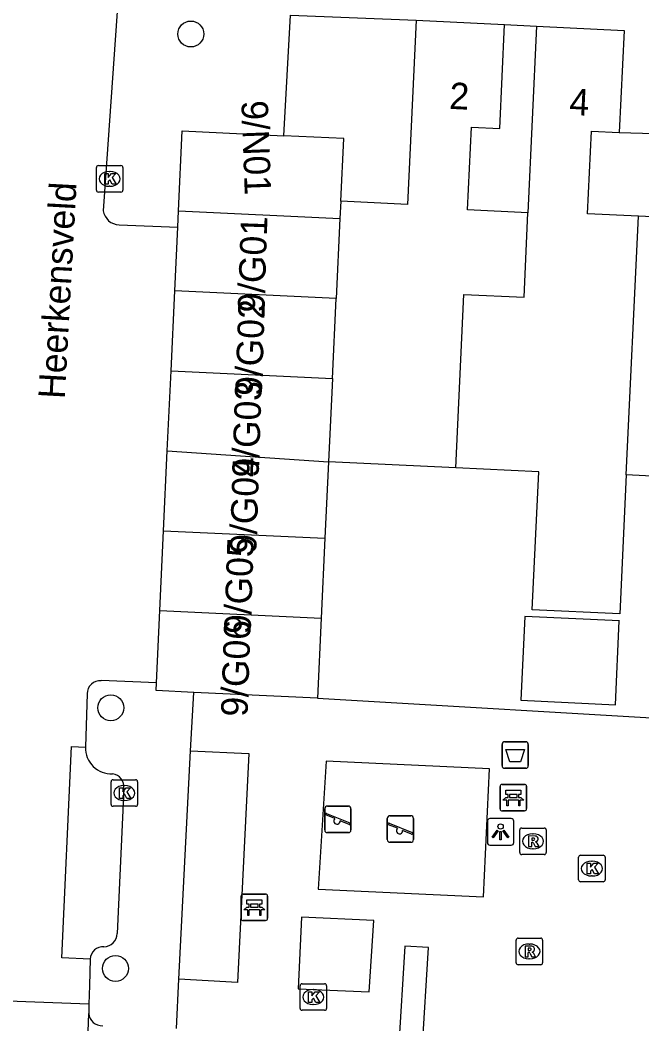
# Model space of a CAD drawing. Extents: x 162990 to 165007, y 383433 to 384336.
# Drawn here: x 164451.53 to 164474.99, y 383661.98 to 383699.84 of the extents above; entities that cross this region are included whole.
import ezdxf

# ---------------------------------------------------------------- set-up
doc = ezdxf.new("R2010")
doc.units = 0
for name, color, linetype in [('IMGEO_Afvalbak', 7, 'Continuous'), ('IMGEO_Bank', 7, 'Continuous'), ('IMGEO_Boom', 7, 'Continuous'), ('IMGEO_Kolk', 7, 'Continuous'), ('IMGEO_Lichtpunt', 7, 'Continuous'), ('IMGEO_Openbare_ruimte_label', 7, 'Continuous'), ('IMGEO_Pand', 7, 'Continuous'), ('IMGEO_Pand_nummerreeks', 7, 'Continuous'), ('IMGEO_Rijbaan_lokaal_open', 7, 'Continuous'), ('IMGEO_Rioolput', 7, 'Continuous'), ('IMGEO_Speelvoorziening', 7, 'Continuous'), ('IMGEO_Voetpad_open', 7, 'Continuous')]:
    doc.layers.add(name, color=color, linetype=linetype)

msp = doc.modelspace()

# ---------------------------------------------------------------- linework, layer by layer
at = {"layer": 'IMGEO_Afvalbak'}
for p, q in [((164469.816, 383672.619), (164470.606, 383672.619)), ((164470.606, 383672.619), (164469.816, 383672.619)), ((164469.716, 383671.719), (164469.716, 383672.519)), ((164469.716, 383672.519), (164469.716, 383671.719)), ((164470.706, 383672.519), (164470.706, 383671.719)), ((164470.706, 383671.719), (164470.706, 383672.519)), ((164470.606, 383671.619), (164469.816, 383671.619)), ((164469.816, 383671.619), (164470.606, 383671.619))]:
    msp.add_line(p, q, dxfattribs=at)
msp.add_lwpolyline([(164469.859, 383672.333), (164470.563, 383672.333), (164470.414, 383671.863), (164470.008, 383671.863), (164469.859, 383672.333)], dxfattribs=at)
for centre, start, end in [((164469.816, 383672.519), 90, 180), ((164469.816, 383672.519), 90, 180), ((164470.606, 383672.519), 0, 90), ((164470.606, 383672.519), 360, 90), ((164469.816, 383671.719), 180, 270), ((164469.816, 383671.719), 180, 270), ((164470.606, 383671.719), 270, 0), ((164470.606, 383671.719), 270, 0)]:
    msp.add_arc(centre, 0.1, start, end, dxfattribs=at)
at = {"layer": 'IMGEO_Bank'}
for p, q in [((164469.642, 383670.089), (164469.642, 383670.93)), ((164469.642, 383670.93), (164469.642, 383670.089)), ((164469.717, 383671.014), (164470.558, 383671.014)), ((164470.558, 383671.014), (164469.717, 383671.014)), ((164470.642, 383670.939), (164470.642, 383670.098)), ((164470.642, 383670.098), (164470.642, 383670.939)), ((164470.339, 383670.412), (164469.946, 383670.412)), ((164469.951, 383670.52), (164469.951, 383670.626)), ((164469.995, 383670.626), (164469.995, 383670.52)), ((164470.283, 383670.632), (164470.001, 383670.632)), ((164470.001, 383670.514), (164470.283, 383670.514)), ((164470.289, 383670.52), (164470.289, 383670.626)), ((164470.333, 383670.626), (164470.333, 383670.52)), ((164470.567, 383670.014), (164469.726, 383670.014)), ((164469.726, 383670.014), (164470.567, 383670.014)), ((164459.87, 383665.953), (164459.87, 383666.794)), ((164459.87, 383666.794), (164459.87, 383665.953)), ((164459.945, 383666.878), (164460.786, 383666.878)), ((164460.786, 383666.878), (164459.945, 383666.878)), ((164460.87, 383666.803), (164460.87, 383665.962)), ((164460.87, 383665.962), (164460.87, 383666.803)), ((164460.567, 383666.276), (164460.174, 383666.276)), ((164460.179, 383666.384), (164460.179, 383666.49)), ((164460.223, 383666.49), (164460.223, 383666.384)), ((164460.511, 383666.496), (164460.229, 383666.496)), ((164460.229, 383666.378), (164460.511, 383666.378)), ((164460.517, 383666.384), (164460.517, 383666.49)), ((164460.561, 383666.49), (164460.561, 383666.384)), ((164460.795, 383665.878), (164459.954, 383665.878)), ((164459.954, 383665.878), (164460.795, 383665.878))]:
    msp.add_line(p, q, dxfattribs=at)
for points in [[(164469.945, 383670.632), (164469.859, 383670.632), (164469.859, 383670.793), (164470.422, 383670.793), (164470.422, 383670.632), (164470.339, 383670.632)], [(164469.889, 383670.412), (164469.747, 383670.412), (164469.859, 383670.514), (164469.945, 383670.514)], [(164469.939, 383670.405), (164469.939, 383670.198), (164469.896, 383670.198), (164469.896, 383670.405)], [(164470.339, 383670.514), (164470.422, 383670.514), (164470.534, 383670.412), (164470.395, 383670.412)], [(164470.389, 383670.405), (164470.389, 383670.198), (164470.345, 383670.198), (164470.345, 383670.405)], [(164460.173, 383666.496), (164460.087, 383666.496), (164460.087, 383666.657), (164460.65, 383666.657), (164460.65, 383666.496), (164460.567, 383666.496)], [(164460.117, 383666.276), (164459.975, 383666.276), (164460.087, 383666.378), (164460.173, 383666.378)], [(164460.167, 383666.269), (164460.167, 383666.062), (164460.124, 383666.062), (164460.124, 383666.269)], [(164460.567, 383666.378), (164460.65, 383666.378), (164460.762, 383666.276), (164460.623, 383666.276)], [(164460.617, 383666.269), (164460.617, 383666.062), (164460.573, 383666.062), (164460.573, 383666.269)]]:
    msp.add_lwpolyline(points, dxfattribs=at)
for centre, radius, start, end in [((164469.72, 383670.936), 0.0779, 92.4484, 184.2845), ((164469.72, 383670.936), 0.0779, 92.4484, 184.2845), ((164470.564, 383670.936), 0.0779, 2.4484, 94.2845), ((164470.564, 383670.936), 0.0779, 2.4484, 94.2845), ((164469.889, 383670.405), 0.00671, 2.8957, 87.1043), ((164469.946, 383670.405), 0.00671, 92.8957, 177.1043), ((164469.944, 383670.625), 0.00671, 2.8957, 87.1043), ((164469.944, 383670.521), 0.00671, 272.8957, 357.1043), ((164470.001, 383670.625), 0.00671, 92.8957, 177.1043), ((164470.001, 383670.521), 0.00671, 182.8957, 267.1043), ((164470.283, 383670.625), 0.00671, 2.8957, 87.1043), ((164470.283, 383670.521), 0.00671, 272.8957, 357.1043), ((164470.34, 383670.625), 0.00671, 92.8957, 177.1043), ((164470.34, 383670.521), 0.00671, 182.8957, 267.1043), ((164470.338, 383670.405), 0.00671, 2.8957, 87.1043), ((164470.395, 383670.405), 0.00671, 92.8957, 177.1043), ((164469.72, 383670.092), 0.0779, 182.4484, 274.2845), ((164469.72, 383670.092), 0.0779, 182.4484, 274.2845), ((164470.564, 383670.092), 0.0779, 272.4484, 4.2845), ((164470.564, 383670.092), 0.0779, 272.4484, 4.2845), ((164459.948, 383666.8), 0.0779, 92.4484, 184.2845), ((164459.948, 383666.8), 0.0779, 92.4484, 184.2845), ((164460.792, 383666.8), 0.0779, 2.4484, 94.2845), ((164460.792, 383666.8), 0.0779, 2.4484, 94.2845), ((164460.117, 383666.269), 0.00671, 2.8957, 87.1043), ((164460.174, 383666.269), 0.00671, 92.8957, 177.1043), ((164460.172, 383666.489), 0.00671, 2.8957, 87.1043), ((164460.172, 383666.385), 0.00671, 272.8957, 357.1043), ((164460.229, 383666.489), 0.00671, 92.8957, 177.1043), ((164460.229, 383666.385), 0.00671, 182.8957, 267.1043), ((164460.511, 383666.489), 0.00671, 2.8957, 87.1043), ((164460.511, 383666.385), 0.00671, 272.8957, 357.1043), ((164460.568, 383666.489), 0.00671, 92.8957, 177.1043), ((164460.568, 383666.385), 0.00671, 182.8957, 267.1043), ((164460.566, 383666.269), 0.00671, 2.8957, 87.1043), ((164460.623, 383666.269), 0.00671, 92.8957, 177.1043), ((164459.948, 383665.956), 0.0779, 182.4484, 274.2845), ((164459.948, 383665.956), 0.0779, 182.4484, 274.2845), ((164460.792, 383665.956), 0.0779, 272.4484, 4.2845), ((164460.792, 383665.956), 0.0779, 272.4484, 4.2845)]:
    msp.add_arc(centre, radius, start, end, dxfattribs=at)
at = {"layer": 'IMGEO_Boom'}
for centre in [(164457.973, 383699.31), (164454.955, 383673.902), (164455.129, 383664.071)]:
    msp.add_circle(centre, 0.489, dxfattribs=at)
at = {"layer": 'IMGEO_Kolk'}
for p, q in [((164454.411, 383693.421), (164454.411, 383694.273)), ((164454.486, 383694.347), (164455.338, 383694.347)), ((164455.412, 383694.273), (164455.412, 383693.421)), ((164454.899, 383694.127), (164454.924, 383694.127)), ((164454.922, 383693.567), (164454.897, 383693.567)), ((164455.338, 383693.347), (164454.486, 383693.347)), ((164454.964, 383670.26), (164454.964, 383671.112)), ((164455.039, 383671.186), (164455.891, 383671.186)), ((164455.965, 383671.112), (164455.965, 383670.26)), ((164455.452, 383670.966), (164455.477, 383670.966)), ((164455.475, 383670.406), (164455.45, 383670.406)), ((164455.891, 383670.186), (164455.039, 383670.186)), ((164472.604, 383667.412), (164472.604, 383668.264)), ((164472.679, 383668.338), (164473.531, 383668.338)), ((164473.092, 383668.118), (164473.117, 383668.118)), ((164473.605, 383668.264), (164473.605, 383667.412)), ((164473.531, 383667.338), (164472.679, 383667.338)), ((164473.115, 383667.558), (164473.09, 383667.558)), ((164462.095, 383662.566), (164462.095, 383663.418)), ((164462.17, 383663.492), (164463.022, 383663.492)), ((164462.583, 383663.272), (164462.608, 383663.272)), ((164463.096, 383663.418), (164463.096, 383662.566)), ((164463.022, 383662.492), (164462.17, 383662.492)), ((164462.606, 383662.712), (164462.581, 383662.712))]:
    msp.add_line(p, q, dxfattribs=at)
for points in [[(164454.411, 383693.421), (164454.411, 383694.273)], [(164454.486, 383694.347), (164455.338, 383694.347)], [(164455.412, 383694.273), (164455.412, 383693.421)], [(164454.732, 383694.047), (164454.855, 383694.047), (164454.855, 383693.896), (164454.985, 383694.047), (164455.149, 383694.047), (164455.003, 383693.896), (164455.156, 383693.647), (164455.004, 383693.647), (164454.919, 383693.811), (164454.855, 383693.744), (164454.855, 383693.647), (164454.732, 383693.647), (164454.732, 383694.047)], [(164455.338, 383693.347), (164454.486, 383693.347)], [(164454.964, 383670.26), (164454.964, 383671.112)], [(164455.039, 383671.186), (164455.891, 383671.186)], [(164455.965, 383671.112), (164455.965, 383670.26)], [(164455.285, 383670.886), (164455.408, 383670.886), (164455.408, 383670.735), (164455.538, 383670.886), (164455.702, 383670.886), (164455.556, 383670.735), (164455.709, 383670.486), (164455.557, 383670.486), (164455.472, 383670.65), (164455.408, 383670.583), (164455.408, 383670.486), (164455.285, 383670.486), (164455.285, 383670.886)], [(164455.891, 383670.186), (164455.039, 383670.186)], [(164472.604, 383667.412), (164472.604, 383668.264)], [(164472.679, 383668.338), (164473.531, 383668.338)], [(164473.605, 383668.264), (164473.605, 383667.412)], [(164472.925, 383668.038), (164473.048, 383668.038), (164473.048, 383667.887), (164473.178, 383668.038), (164473.342, 383668.038), (164473.196, 383667.887), (164473.349, 383667.638), (164473.197, 383667.638), (164473.112, 383667.802), (164473.048, 383667.735), (164473.048, 383667.638), (164472.925, 383667.638), (164472.925, 383668.038)], [(164473.531, 383667.338), (164472.679, 383667.338)], [(164462.095, 383662.566), (164462.095, 383663.418)], [(164462.17, 383663.492), (164463.022, 383663.492)], [(164462.416, 383663.192), (164462.539, 383663.192), (164462.539, 383663.041), (164462.669, 383663.192), (164462.833, 383663.192), (164462.687, 383663.041), (164462.84, 383662.792), (164462.688, 383662.792), (164462.603, 383662.956), (164462.539, 383662.889), (164462.539, 383662.792), (164462.416, 383662.792), (164462.416, 383663.192)], [(164463.096, 383663.418), (164463.096, 383662.566)], [(164463.022, 383662.492), (164462.17, 383662.492)]]:
    msp.add_lwpolyline(points, dxfattribs=at)
for centre, start, end in [((164454.488, 383694.271), 91.552, 178.448), ((164454.488, 383694.271), 91.552, 178.448), ((164455.336, 383694.271), 1.552, 88.448), ((164455.336, 383694.271), 1.552, 88.448), ((164454.488, 383693.423), 181.552, 268.448), ((164454.488, 383693.423), 181.552, 268.448), ((164455.336, 383693.423), 271.552, 358.448), ((164455.336, 383693.423), 271.552, 358.448), ((164455.041, 383671.11), 91.552, 178.448), ((164455.041, 383671.11), 91.552, 178.448), ((164455.889, 383671.11), 1.552, 88.448), ((164455.889, 383671.11), 1.552, 88.448), ((164455.041, 383670.262), 181.552, 268.448), ((164455.041, 383670.262), 181.552, 268.448), ((164455.889, 383670.262), 271.552, 358.448), ((164455.889, 383670.262), 271.552, 358.448), ((164472.681, 383668.262), 91.552, 178.448), ((164472.681, 383668.262), 91.552, 178.448), ((164473.529, 383668.262), 1.552, 88.448), ((164473.529, 383668.262), 1.552, 88.448), ((164472.681, 383667.414), 181.552, 268.448), ((164472.681, 383667.414), 181.552, 268.448), ((164473.529, 383667.414), 271.552, 358.448), ((164473.529, 383667.414), 271.552, 358.448), ((164462.172, 383663.416), 91.552, 178.448), ((164462.172, 383663.416), 91.552, 178.448), ((164463.02, 383663.416), 1.552, 88.448), ((164463.02, 383663.416), 1.552, 88.448), ((164462.172, 383662.568), 181.552, 268.448), ((164462.172, 383662.568), 181.552, 268.448), ((164463.02, 383662.568), 271.552, 358.448), ((164463.02, 383662.568), 271.552, 358.448)]:
    msp.add_arc(centre, 0.0765, start, end, dxfattribs=at)
for centre, major_axis, ratio, start_param, end_param in [((164454.898, 383693.847), (-0.387, 0.002), 0.722429, 4.712389, 7.853982), ((164454.923, 383693.847), (-0.39, 0.002), 0.717154, 1.570796, 4.712389), ((164455.451, 383670.686), (-0.387, 0.002), 0.722429, 4.712389, 7.853982), ((164455.476, 383670.686), (-0.39, 0.002), 0.717154, 1.570796, 4.712389), ((164473.091, 383667.838), (-0.387, 0.002), 0.722429, 4.712389, 7.853982), ((164473.116, 383667.838), (-0.39, 0.002), 0.717154, 1.570796, 4.712389), ((164462.582, 383662.992), (-0.387, 0.002), 0.722429, 4.712389, 7.853982), ((164462.607, 383662.992), (-0.39, 0.002), 0.717154, 1.570796, 4.712389)]:
    msp.add_ellipse(centre, major_axis=major_axis, ratio=ratio, start_param=start_param, end_param=end_param, dxfattribs=at)
at = {"layer": 'IMGEO_Lichtpunt'}
for p, q in [((164469.16, 383669.625), (164469.16, 383668.818)), ((164469.16, 383669.625), (164469.16, 383668.818)), ((164470.062, 383669.72), (164469.254, 383669.72)), ((164470.062, 383669.72), (164469.254, 383669.72)), ((164470.156, 383668.818), (164470.156, 383669.625)), ((164470.156, 383668.818), (164470.156, 383669.625)), ((164469.254, 383668.724), (164470.062, 383668.724)), ((164469.254, 383668.724), (164470.062, 383668.724))]:
    msp.add_line(p, q, dxfattribs=at)
for points in [[(164469.534, 383669.289), (164469.573, 383669.261), (164469.385, 383668.999), (164469.347, 383669.026), (164469.534, 383669.289)], [(164469.636, 383669.241), (164469.683, 383669.241), (164469.683, 383668.919), (164469.636, 383668.919), (164469.636, 383669.241)], [(164469.746, 383669.261), (164469.784, 383669.288), (164469.971, 383669.026), (164469.932, 383668.998), (164469.746, 383669.261)]]:
    msp.add_lwpolyline(points, dxfattribs=at)
msp.add_circle((164469.659, 383669.423), 0.0994, dxfattribs=at)
for centre, start, end in [((164469.254, 383669.625), 90, 180), ((164469.254, 383669.625), 90, 180), ((164470.062, 383669.625), 0, 90), ((164470.062, 383669.625), 0, 90), ((164469.254, 383668.818), 180, 270), ((164469.254, 383668.818), 180, 270), ((164470.062, 383668.818), 270, 0), ((164470.062, 383668.818), 270, 360)]:
    msp.add_arc(centre, 0.0946, start, end, dxfattribs=at)
at = {"layer": 'IMGEO_Pand'}
for points in [[(164466.471, 383699.831), (164466.145, 383692.884), (164463.632, 383693.002)], [(164466.471, 383699.831), (164469.812, 383699.674)], [(164470.688, 383692.567), (164468.417, 383692.674), (164468.564, 383695.797), (164469.628, 383695.747), (164469.812, 383699.674)], [(164471.017, 383699.602), (164470.688, 383692.567)], [(164471.017, 383699.602), (164474.319, 383699.447), (164474.138, 383695.599)], [(164457.509, 383692.64), (164457.65, 383695.653), (164461.477, 383695.473)], [(164463.632, 383693.002), (164463.742, 383695.367), (164461.477, 383695.473)], [(164474.857, 383692.435), (164472.943, 383692.525), (164473.089, 383695.648), (164474.138, 383695.599)], [(164477.653, 383695.492), (164477.504, 383692.311), (164474.857, 383692.435)], [(164463.632, 383693.002), (164463.601, 383692.35)], [(164457.48, 383692.025), (164457.509, 383692.64)], [(164457.509, 383692.64), (164463.601, 383692.35)], [(164463.601, 383692.35), (164463.459, 383689.339)], [(164467.966, 383682.951), (164468.268, 383689.487), (164470.543, 383689.382), (164470.688, 383692.567)], [(164474.398, 383682.68), (164474.857, 383692.435)], [(164457.367, 383689.625), (164457.48, 383692.025)], [(164457.226, 383686.61), (164457.367, 383689.625)], [(164463.459, 383689.339), (164457.367, 383689.625)], [(164463.318, 383686.324), (164463.459, 383689.339)], [(164457.085, 383683.595), (164457.226, 383686.61)], [(164457.226, 383686.61), (164463.318, 383686.324)], [(164463.318, 383686.324), (164463.17, 383683.175)], [(164456.944, 383680.58), (164457.085, 383683.595)], [(164457.085, 383683.595), (164463.17, 383683.175)], [(164463.17, 383683.175), (164463.035, 383680.294)], [(164467.966, 383682.951), (164463.17, 383683.175)], [(164474.398, 383682.68), (164474.152, 383677.44), (164470.854, 383677.595), (164471.098, 383682.804), (164467.966, 383682.951)], [(164481.543, 383682.345), (164476.098, 383682.6), (164474.398, 383682.68)], [(164456.802, 383677.565), (164456.944, 383680.58)], [(164456.944, 383680.58), (164463.035, 383680.294)], [(164463.035, 383680.294), (164462.894, 383677.279)], [(164456.675, 383674.845), (164456.802, 383677.565)], [(164456.802, 383677.565), (164462.894, 383677.279)], [(164462.894, 383677.279), (164462.753, 383674.265)], [(164474.14, 383677.178), (164470.573, 383677.346), (164470.425, 383674.185), (164473.991, 383674.018), (164474.139, 383677.175), (164474.14, 383677.178)], [(164458.084, 383674.483), (164456.661, 383674.55), (164456.675, 383674.845)], [(164462.753, 383674.265), (164458.084, 383674.483)]]:
    msp.add_lwpolyline(points, dxfattribs=at)
at = {"layer": 'IMGEO_Rijbaan_lokaal_open'}
for points in [[(164455.418, 383703.384), (164454.671, 383692.644)], [(164455.267, 383692.112), (164457.48, 383692.025)], [(164456.675, 383674.845), (164454.586, 383674.924)], [(164454.064, 383674.434), (164453.997, 383672.413)], [(164454.18, 383664.424), (164453.109, 383664.471), (164453.477, 383672.438), (164453.997, 383672.413)], [(164454.18, 383664.424), (164454.153, 383663.425), (164454.132, 383662.728)], [(164454.132, 383662.728), (164449.027, 383662.918)], [(164454.132, 383662.728), (164454.122, 383662.373)], [(164453.782, 383654.244), (164454.005, 383658.942), (164454.122, 383662.373)]]:
    msp.add_lwpolyline(points, dxfattribs=at)
for centre, radius, start, end in [((164455.289, 383692.736), 0.624, 188.4751, 268.0196), ((164454.561, 383674.427), 0.497, 87.1463, 179.2315)]:
    msp.add_arc(centre, radius, start, end, dxfattribs=at)
at = {"layer": 'IMGEO_Rioolput'}
for p, q in [((164470.38, 383668.441), (164470.38, 383669.293)), ((164470.455, 383669.367), (164471.307, 383669.367)), ((164471.381, 383669.293), (164471.381, 383668.441)), ((164470.868, 383669.147), (164470.893, 383669.147)), ((164470.891, 383668.587), (164470.866, 383668.587)), ((164471.307, 383668.367), (164470.455, 383668.367)), ((164470.245, 383664.287), (164470.245, 383665.139)), ((164470.32, 383665.213), (164471.172, 383665.213)), ((164471.246, 383665.139), (164471.246, 383664.287)), ((164470.733, 383664.993), (164470.758, 383664.993)), ((164470.756, 383664.433), (164470.731, 383664.433)), ((164471.172, 383664.213), (164470.32, 383664.213))]:
    msp.add_line(p, q, dxfattribs=at)
for points in [[(164470.38, 383668.441), (164470.38, 383669.293)], [(164470.455, 383669.367), (164471.307, 383669.367)], [(164471.381, 383669.293), (164471.381, 383668.441)], [(164470.969, 383669.065), (164470.717, 383669.067), (164470.717, 383668.667)], [(164470.717, 383668.667), (164470.841, 383668.667), (164470.841, 383668.829), (164470.852, 383668.829)], [(164470.895, 383668.986), (164470.841, 383668.986), (164470.841, 383668.905)], [(164470.841, 383668.905), (164470.893, 383668.905)], [(164470.899, 383668.8), (164470.97, 383668.667), (164471.11, 383668.667), (164471.045, 383668.793)], [(164471.307, 383668.367), (164470.455, 383668.367)], [(164470.245, 383664.287), (164470.245, 383665.139)], [(164470.32, 383665.213), (164471.172, 383665.213)], [(164471.246, 383665.139), (164471.246, 383664.287)], [(164470.834, 383664.911), (164470.582, 383664.913), (164470.582, 383664.513)], [(164470.582, 383664.513), (164470.706, 383664.513), (164470.706, 383664.675), (164470.717, 383664.675)], [(164470.76, 383664.832), (164470.706, 383664.832), (164470.706, 383664.751)], [(164470.706, 383664.751), (164470.758, 383664.751)], [(164470.764, 383664.646), (164470.835, 383664.513), (164470.975, 383664.513), (164470.91, 383664.639)], [(164471.172, 383664.213), (164470.32, 383664.213)]]:
    msp.add_lwpolyline(points, dxfattribs=at)
for centre, radius, start, end in [((164470.457, 383669.291), 0.0765, 91.552, 178.448), ((164470.457, 383669.291), 0.0765, 91.552, 178.448), ((164471.305, 383669.291), 0.0765, 1.552, 88.448), ((164471.305, 383669.291), 0.0765, 1.552, 88.448), ((164470.851, 383668.776), 0.0533, 26.0293, 88.6989), ((164470.877, 383669.094), 0.19, 274.7715, 282.9687), ((164470.901, 383668.89), 0.0964, 77.0061, 93.1865), ((164470.915, 383668.947), 0.0378, 276.6634, 79.6772), ((164470.968, 383668.955), 0.109, 350.3612, 89.416), ((164470.966, 383668.955), 0.112, 277.5842, 350.9817), ((164470.95, 383668.74), 0.108, 29.5134, 73.7905), ((164470.457, 383668.443), 0.0765, 181.552, 268.448), ((164470.457, 383668.443), 0.0765, 181.552, 268.448), ((164471.305, 383668.443), 0.0765, 271.552, 358.448), ((164471.305, 383668.443), 0.0765, 271.552, 358.448), ((164470.322, 383665.137), 0.0765, 91.552, 178.448), ((164470.322, 383665.137), 0.0765, 91.552, 178.448), ((164471.17, 383665.137), 0.0765, 1.552, 88.448), ((164471.17, 383665.137), 0.0765, 1.552, 88.448), ((164470.716, 383664.622), 0.0533, 26.0293, 88.6989), ((164470.742, 383664.94), 0.19, 274.7715, 282.9687), ((164470.766, 383664.736), 0.0964, 77.0061, 93.1865), ((164470.78, 383664.793), 0.0378, 276.6634, 79.6772), ((164470.833, 383664.801), 0.109, 350.3612, 89.416), ((164470.831, 383664.801), 0.112, 277.5842, 350.9817), ((164470.815, 383664.586), 0.108, 29.5134, 73.7905), ((164470.322, 383664.289), 0.0765, 181.552, 268.448), ((164470.322, 383664.289), 0.0765, 181.552, 268.448), ((164471.17, 383664.289), 0.0765, 271.552, 358.448), ((164471.17, 383664.289), 0.0765, 271.552, 358.448)]:
    msp.add_arc(centre, radius, start, end, dxfattribs=at)
for centre, major_axis, ratio, start_param, end_param in [((164470.867, 383668.867), (-0.387, 0.002), 0.722429, 4.712389, 7.853982), ((164470.892, 383668.867), (-0.39, 0.002), 0.717154, 1.570796, 4.712389), ((164470.732, 383664.713), (-0.387, 0.002), 0.722429, 4.712389, 7.853982), ((164470.757, 383664.713), (-0.39, 0.002), 0.717154, 1.570796, 4.712389)]:
    msp.add_ellipse(centre, major_axis=major_axis, ratio=ratio, start_param=start_param, end_param=end_param, dxfattribs=at)
at = {"layer": 'IMGEO_Speelvoorziening'}
for p, q in [((164463.026, 383669.293), (164463.026, 383670.093)), ((164463.026, 383670.093), (164463.026, 383669.293)), ((164463.126, 383670.193), (164463.916, 383670.193)), ((164463.916, 383670.193), (164463.126, 383670.193)), ((164464.016, 383670.093), (164464.016, 383669.293)), ((164464.016, 383669.293), (164464.016, 383670.093)), ((164463.409, 383669.721), (164463.07, 383669.858)), ((164463.095, 383669.918), (164463.971, 383669.565)), ((164463.947, 383669.505), (164463.607, 383669.642)), ((164465.383, 383668.928), (164465.383, 383669.728)), ((164465.383, 383669.728), (164465.383, 383668.928)), ((164465.483, 383669.828), (164466.273, 383669.828)), ((164466.273, 383669.828), (164465.483, 383669.828)), ((164466.373, 383669.728), (164466.373, 383668.928)), ((164466.373, 383668.928), (164466.373, 383669.728)), ((164463.916, 383669.193), (164463.126, 383669.193)), ((164463.126, 383669.193), (164463.916, 383669.193)), ((164465.766, 383669.356), (164465.427, 383669.493)), ((164465.452, 383669.553), (164466.328, 383669.2)), ((164466.304, 383669.14), (164465.964, 383669.277)), ((164466.273, 383668.828), (164465.483, 383668.828)), ((164465.483, 383668.828), (164466.273, 383668.828))]:
    msp.add_line(p, q, dxfattribs=at)
for centre, radius, start, end in [((164463.126, 383670.093), 0.1, 90, 180), ((164463.126, 383670.093), 0.1, 90, 180), ((164463.916, 383670.093), 0.1, 0, 90), ((164463.916, 383670.093), 0.1, 360, 90), ((164463.083, 383669.888), 0.0327, 68.078, 248.078), ((164463.488, 383669.631), 0.12, 130.9928, 5.1632), ((164465.483, 383669.728), 0.1, 90, 180), ((164465.483, 383669.728), 0.1, 90, 180), ((164466.273, 383669.728), 0.1, 0, 90), ((164466.273, 383669.728), 0.1, 360, 90), ((164463.126, 383669.293), 0.1, 180, 270), ((164463.126, 383669.293), 0.1, 180, 270), ((164463.916, 383669.293), 0.1, 270, 0), ((164463.916, 383669.293), 0.1, 270, 0), ((164463.959, 383669.535), 0.0327, 248.078, 68.078), ((164465.44, 383669.523), 0.0327, 68.078, 248.078), ((164465.845, 383669.266), 0.12, 130.9928, 5.1632), ((164466.316, 383669.17), 0.0327, 248.078, 68.078), ((164465.483, 383668.928), 0.1, 180, 270), ((164465.483, 383668.928), 0.1, 180, 270), ((164466.273, 383668.928), 0.1, 270, 0), ((164466.273, 383668.928), 0.1, 270, 0)]:
    msp.add_arc(centre, radius, start, end, dxfattribs=at)
at = {"layer": 'IMGEO_Voetpad_open'}
for points in [[(164461.477, 383695.473), (164461.74, 383700.022), (164466.471, 383699.831)], [(164469.812, 383699.674), (164471.017, 383699.602)], [(164474.138, 383695.599), (164477.653, 383695.492)], [(164457.962, 383672.272), (164458.084, 383674.483)], [(164462.753, 383674.265), (164477.272, 383673.411)], [(164457.962, 383672.272), (164460.167, 383672.176), (164459.737, 383663.541), (164457.526, 383663.661)], [(164457.526, 383663.661), (164457.962, 383672.272)], [(164462.778, 383667.067), (164469.019, 383666.766), (164469.24, 383671.603), (164463.079, 383671.884), (164462.778, 383667.067)], [(164455.446, 383670.854), (164455.194, 383665.388)], [(164462.022, 383663.303), (164464.704, 383663.188), (164464.88, 383665.881), (164462.152, 383666.003), (164462.022, 383663.303)], [(164465.814, 383661.012), (164466.705, 383660.965), (164466.937, 383664.855), (164466.042, 383664.911), (164465.814, 383661.012)], [(164457.432, 383661.812), (164457.526, 383663.661)]]:
    msp.add_lwpolyline(points, dxfattribs=at)
for centre, radius, start, end in [((164454.978, 383672.393), 0.982, 178.816, 272.4295), ((164454.952, 383670.919), 0.498, 352.5234, 82.1958), ((164454.687, 383665.397), 0.507, 271.1572, 358.958), ((164454.656, 383664.416), 0.476, 85.0771, 178.983), ((164454.637, 383662.427), 0.518, 185.9722, 271.3028)]:
    msp.add_arc(centre, radius, start, end, dxfattribs=at)

# ---------------------------------------------------------------- texts
at = {"layer": 'IMGEO_Openbare_ruimte_label'}
msp.add_text('Heerkensveld', height=1, rotation=86.8488, dxfattribs=at).set_placement((164453.216, 383685.532))
at = {"layer": 'IMGEO_Pand_nummerreeks'}
for s, rotation, p in [('2', 357.3095, (164467.71, 383696.489)), ('4', 357.3124, (164472.239, 383696.261)), ('9/N01', 272.1211, (164459.878, 383696.789)), ('9/G01', 88.0189, (164460.741, 383688.788)), ('9/G02', 88.0189, (164460.648, 383685.647)), ('9/G03', 88.0189, (164460.528, 383682.569)), ('9/G04', 88.0189, (164460.438, 383679.694)), ('9/G05', 88.0189, (164460.228, 383676.669)), ('9/G06', 88.0189, (164460.109, 383673.554))]:
    msp.add_text(s, height=1, rotation=rotation, dxfattribs=at).set_placement(p)

doc.saveas('drawing.dxf')
